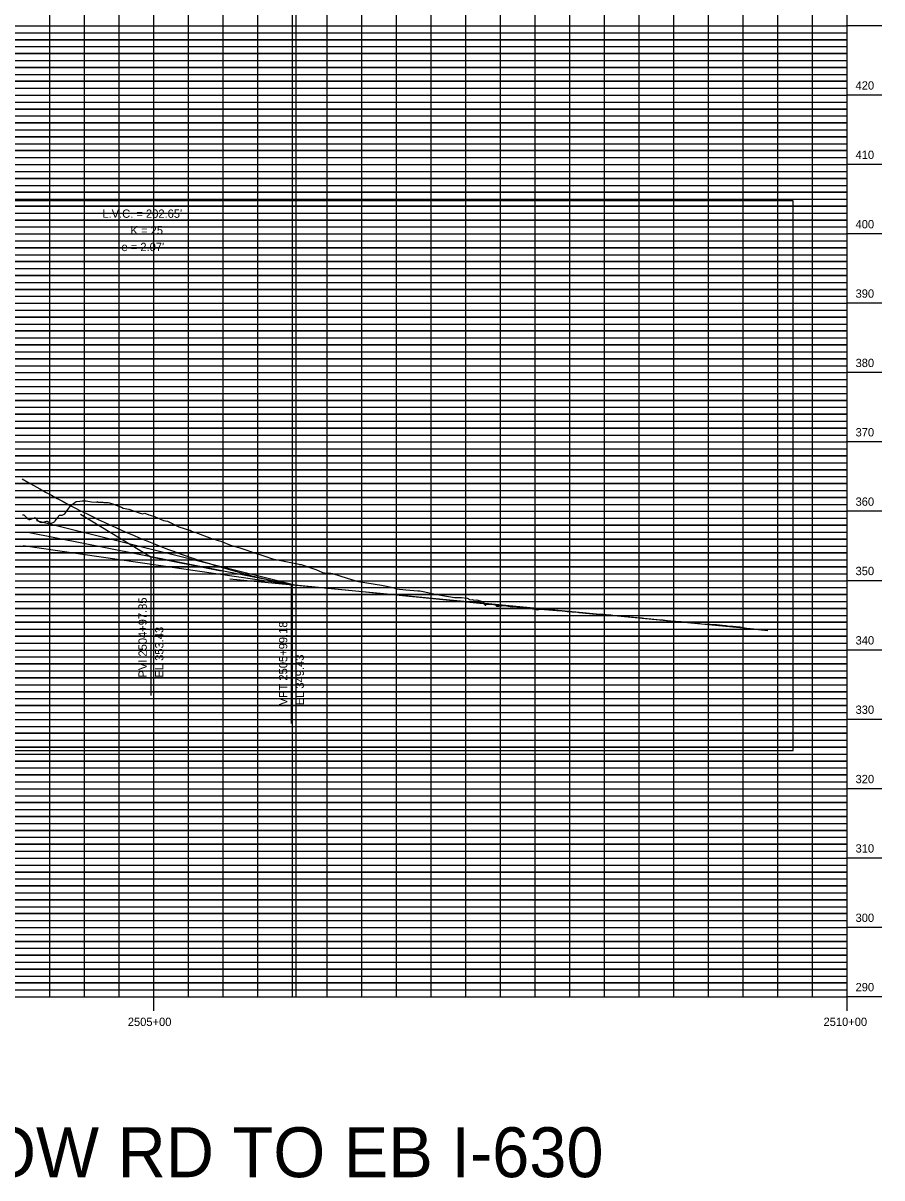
# Model space of a CAD drawing. Extents: x 1195880 to 1289360, y 2059330 to 2086925.
# Drawn here: x 1203520 to 1204139, y 2064734 to 2065566 of the extents above; entities that cross this region are included whole.
import ezdxf

# ---------------------------------------------------------------- set-up
doc = ezdxf.new("R2010")
doc.units = 0
for name, color, linetype in [('Clip', 7, 'Continuous'), ('Default', 7, 'Continuous'), ('Existing Ground PGL', 7, 'Continuous'), ('Grid', 7, 'Continuous'), ('Grid Lables', 7, 'Continuous'), ('Profile', 7, 'Continuous'), ('Profile Annotation', 7, 'Continuous')]:
    doc.layers.add(name, color=color, linetype=linetype)

msp = doc.modelspace()

# ---------------------------------------------------------------- linework, layer by layer
at = {"layer": 'Clip'}
msp.add_lwpolyline([(1203093.54, 2065041.86), (1204075.43, 2065041.86), (1204075.43, 2065438.05), (1203093.54, 2065438.05)], close=True, dxfattribs=at)
at = {"layer": 'Default'}
for p, q in [((1203716.87, 2064864.18), (1203716.87, 2065703.18)), ((1203716.87, 2065160.67), (1203529.66, 2065207.28)), ((1203716.87, 2065160.67), (1203524.56, 2065198.61)), ((1203716.87, 2065160.67), (1203520.08, 2065189.42)), ((1204057.18, 2065128.21), (1203669.12, 2065165.23)), ((1203614.36, 2064864.18), (1203716.87, 2064864.18))]:
    msp.add_line(p, q, dxfattribs=at)
at = {"layer": 'Existing Ground PGL'}
msp.add_lwpolyline([(1203519.52, 2065211.66), (1203520.46, 2065211.74), (1203520.61, 2065211.62), (1203522.65, 2065209.38), (1203523.15, 2065208.83), (1203523.62, 2065208.87), (1203523.67, 2065208.78), (1203524.39, 2065208.35), (1203524.91, 2065208.24), (1203526.32, 2065208.83), (1203527.53, 2065209.22), (1203528.75, 2065209.63), (1203530.61, 2065207.25), (1203532.4, 2065206.34), (1203532.97, 2065206.05), (1203534.42, 2065206.28), (1203537.21, 2065207.04), (1203537.28, 2065207), (1203539.88, 2065205.6), (1203540.6, 2065205.7), (1203542.16, 2065206.39), (1203542.42, 2065206.51), (1203542.84, 2065206.8), (1203543.12, 2065207.26), (1203545.24, 2065210.03), (1203545.66, 2065210.55), (1203546.12, 2065211.4), (1203547.03, 2065211.41), (1203547.66, 2065211.43), (1203548.21, 2065211.33), (1203550.13, 2065212.47), (1203551.91, 2065214.87), (1203553.04, 2065216.38), (1203554.43, 2065218.3), (1203558.21, 2065221.18), (1203560.91, 2065221.52), (1203562.58, 2065221.65), (1203565.58, 2065221.81), (1203569.27, 2065221.13), (1203573.14, 2065220.86), (1203573.47, 2065221.15), (1203574.04, 2065220.87), (1203576.15, 2065220.79), (1203577.58, 2065220.69), (1203578.35, 2065220.48), (1203581.5, 2065220.47), (1203582.25, 2065220.22), (1203583.68, 2065219.71), (1203584.02, 2065219.91), (1203584.29, 2065219.55), (1203585.33, 2065219.36), (1203591.05, 2065217.07), (1203592.16, 2065216.45), (1203596.37, 2065215.83), (1203604.47, 2065212.74), (1203606.26, 2065212.26), (1203607.82, 2065212.74), (1203610.63, 2065211.65), (1203611.59, 2065211.48), (1203614.74, 2065210.47), (1203621.27, 2065207.68), (1203624.05, 2065206.99), (1203632.39, 2065202.99), (1203640.01, 2065200.58), (1203640.41, 2065200.58), (1203641.41, 2065199.79), (1203643, 2065199.39), (1203644.6, 2065199.02), (1203655.78, 2065194.59), (1203657.17, 2065194.44), (1203660.71, 2065193.16), (1203660.8, 2065193.12), (1203662.71, 2065192.57), (1203669.55, 2065189.85), (1203676.24, 2065187.77), (1203689.07, 2065183.62), (1203690.83, 2065183.15), (1203693.65, 2065182.2), (1203694.48, 2065181.74), (1203699.98, 2065180.01), (1203717.93, 2065176.23), (1203718.97, 2065176), (1203719.37, 2065175.87), (1203719.44, 2065175.84), (1203719.57, 2065175.82), (1203720.59, 2065175.79), (1203721.27, 2065175.6), (1203730.31, 2065172.4), (1203732.26, 2065171.88), (1203736.35, 2065169.91), (1203737.47, 2065169.78), (1203742.05, 2065169.56), (1203743.13, 2065169.36), (1203753.73, 2065165.97), (1203759.15, 2065164.43), (1203760.81, 2065163.89), (1203761.98, 2065163.57), (1203778.53, 2065161.04), (1203786.72, 2065159.2), (1203789.2, 2065158.31), (1203796.16, 2065157.52), (1203804.73, 2065156.84), (1203806.18, 2065156.89), (1203808.5, 2065156.35), (1203818.45, 2065154.33), (1203825.39, 2065152.97), (1203831.2, 2065152.12), (1203831.95, 2065151.97), (1203834.22, 2065152.06), (1203836.08, 2065152.13), (1203840.31, 2065151.62), (1203841.1, 2065151.4), (1203841.54, 2065150.87), (1203842.54, 2065150.44), (1203844.09, 2065150.68), (1203844.2, 2065150.6), (1203845.08, 2065150.19), (1203847.15, 2065150.29), (1203850.98, 2065149.19), (1203852.01, 2065148), (1203853.21, 2065146.58), (1203853.78, 2065146.65), (1203853.94, 2065147.27), (1203860.24, 2065147.3), (1203861.49, 2065145.88), (1203863.16, 2065145.92), (1203867.28, 2065146.25), (1203869.83, 2065145.75), (1203872.71, 2065145.3), (1203875.64, 2065145.59), (1203879.93, 2065144.23), (1203887.3, 2065143.79), (1203889.32, 2065143.72), (1203890.72, 2065143.27), (1203893.11, 2065143.54), (1203904.97, 2065142.6), (1203905.23, 2065142.63), (1203905.56, 2065142.62), (1203905.79, 2065142.61), (1203905.98, 2065142.62), (1203906.29, 2065142.68), (1203910.93, 2065142.18), (1203912.4, 2065142.02), (1203915.85, 2065141.8), (1203917.87, 2065141.66), (1203919.8, 2065141.43), (1203920.77, 2065141.31), (1203921.22, 2065141.26), (1203922.07, 2065141.13), (1203923.37, 2065140.95), (1203925.69, 2065140.76), (1203930.6, 2065140.35), (1203933.24, 2065140.13), (1203933.75, 2065140.14), (1203934.47, 2065140.13), (1203935.5, 2065140.12), (1203935.52, 2065140.12), (1203936.37, 2065140.12), (1203938.43, 2065139.93), (1203939.51, 2065139.84), (1203940.44, 2065139.76), (1203943.8, 2065139.45), (1203945.36, 2065139.32), (1203948.21, 2065139.07), (1203950.28, 2065138.91), (1203950.82, 2065138.87), (1203951.47, 2065138.79), (1203952.7, 2065138.65), (1203954.11, 2065138.51), (1203955.14, 2065138.38), (1203955.2, 2065138.38), (1203960.12, 2065137.92), (1203965.04, 2065137.46), (1203965.54, 2065137.42), (1203966.24, 2065137.41), (1203966.53, 2065137.39), (1203967.68, 2065137.26), (1203969.95, 2065136.99), (1203970.18, 2065136.96), (1203971.75, 2065136.76), (1203972.82, 2065136.66), (1203973.58, 2065136.56), (1203974.87, 2065136.43), (1203979.79, 2065135.92), (1203979.8, 2065135.92), (1203980.08, 2065135.9), (1203980.5, 2065135.91), (1203981.18, 2065135.89), (1203981.55, 2065135.88), (1203984.71, 2065135.59), (1203984.83, 2065135.57), (1203989.63, 2065135.12), (1203990.49, 2065135.04), (1203994.55, 2065134.65), (1203994.63, 2065134.64), (1203996.56, 2065134.45), (1203999.47, 2065134.16), (1204004.39, 2065133.67), (1204006.75, 2065133.44), (1204009.31, 2065133.18), (1204013.29, 2065132.95), (1204015.54, 2065132.8), (1204017.68, 2065132.65), (1204019.04, 2065132.55), (1204019.98, 2065132.48), (1204026.49, 2065131.81), (1204026.74, 2065131.77), (1204027.11, 2065131.69), (1204027.69, 2065131.57), (1204028.28, 2065131.44), (1204030.53, 2065131.38), (1204031.97, 2065131.34), (1204034.29, 2065131.17), (1204037.22, 2065130.84), (1204038.18, 2065130.66), (1204040.22, 2065130.31), (1204043.28, 2065129.76), (1204052.47, 2065128.73), (1204057.18, 2065128.21)], dxfattribs=at)
at = {"layer": 'Grid'}
for p, q in [((1203539.36, 2064864.18), (1203539.36, 2065664.18)), ((1203564.36, 2064864.18), (1203564.36, 2065664.18)), ((1203589.36, 2064864.18), (1203589.36, 2065664.18)), ((1203614.36, 2064864.18), (1203614.36, 2065664.18)), ((1203639.36, 2064864.18), (1203639.36, 2065664.18)), ((1203664.36, 2064864.18), (1203664.36, 2065664.18)), ((1203689.36, 2064864.18), (1203689.36, 2065664.18)), ((1203714.36, 2064864.18), (1203714.36, 2065664.18)), ((1203739.36, 2064864.18), (1203739.36, 2065664.18)), ((1203764.36, 2064864.18), (1203764.36, 2065664.18)), ((1203789.36, 2064864.18), (1203789.36, 2065664.18)), ((1203814.36, 2064864.18), (1203814.36, 2065664.18)), ((1203839.36, 2064864.18), (1203839.36, 2065664.18)), ((1203864.36, 2064864.18), (1203864.36, 2065664.18)), ((1203889.36, 2064864.18), (1203889.36, 2065664.18)), ((1203914.36, 2064864.18), (1203914.36, 2065664.18)), ((1203939.36, 2064864.18), (1203939.36, 2065664.18)), ((1203964.36, 2064864.18), (1203964.36, 2065664.18)), ((1203989.36, 2064864.18), (1203989.36, 2065664.18)), ((1204014.36, 2064864.18), (1204014.36, 2065664.18)), ((1204039.36, 2064864.18), (1204039.36, 2065664.18)), ((1204064.36, 2064864.18), (1204064.36, 2065664.18)), ((1204089.36, 2064864.18), (1204089.36, 2065664.18)), ((1204114.36, 2064864.18), (1204114.36, 2065664.18)), ((1203114.36, 2065564.18), (1204114.36, 2065564.18)), ((1203114.36, 2065559.18), (1204114.36, 2065559.18)), ((1204139.36, 2065564.18), (1204114.36, 2065564.18)), ((1203114.36, 2065554.18), (1204114.36, 2065554.18)), ((1204114.36, 2065554.18), (1203114.36, 2065554.18)), ((1203114.36, 2065549.18), (1204114.36, 2065549.18)), ((1203114.36, 2065544.18), (1204114.36, 2065544.18)), ((1204114.36, 2065544.18), (1203114.36, 2065544.18)), ((1203114.36, 2065539.18), (1204114.36, 2065539.18)), ((1203114.36, 2065534.18), (1204114.36, 2065534.18)), ((1204114.36, 2065534.18), (1203114.36, 2065534.18)), ((1203114.36, 2065529.18), (1204114.36, 2065529.18)), ((1203114.36, 2065524.18), (1204114.36, 2065524.18)), ((1204114.36, 2065524.18), (1203114.36, 2065524.18)), ((1203114.36, 2065519.18), (1204114.36, 2065519.18)), ((1203114.36, 2065514.18), (1204114.36, 2065514.18)), ((1203114.36, 2065509.18), (1204114.36, 2065509.18)), ((1204139.36, 2065514.18), (1204114.36, 2065514.18)), ((1203114.36, 2065504.18), (1204114.36, 2065504.18)), ((1204114.36, 2065504.18), (1203114.36, 2065504.18)), ((1203114.36, 2065499.18), (1204114.36, 2065499.18)), ((1203114.36, 2065494.18), (1204114.36, 2065494.18)), ((1204114.36, 2065494.18), (1203114.36, 2065494.18)), ((1203114.36, 2065489.18), (1204114.36, 2065489.18)), ((1203114.36, 2065484.18), (1204114.36, 2065484.18)), ((1204114.36, 2065484.18), (1203114.36, 2065484.18)), ((1203114.36, 2065479.18), (1204114.36, 2065479.18)), ((1203114.36, 2065474.18), (1204114.36, 2065474.18)), ((1204114.36, 2065474.18), (1203114.36, 2065474.18)), ((1203114.36, 2065469.18), (1204114.36, 2065469.18)), ((1203114.36, 2065464.18), (1204114.36, 2065464.18)), ((1203114.36, 2065459.18), (1204114.36, 2065459.18)), ((1204139.36, 2065464.18), (1204114.36, 2065464.18)), ((1203114.36, 2065454.18), (1204114.36, 2065454.18)), ((1204114.36, 2065454.18), (1203114.36, 2065454.18)), ((1203114.36, 2065449.18), (1204114.36, 2065449.18)), ((1203114.36, 2065444.18), (1204114.36, 2065444.18)), ((1204114.36, 2065444.18), (1203114.36, 2065444.18)), ((1203114.36, 2065439.18), (1204114.36, 2065439.18)), ((1203114.36, 2065434.18), (1204114.36, 2065434.18)), ((1204114.36, 2065434.18), (1203114.36, 2065434.18)), ((1203114.36, 2065429.18), (1204114.36, 2065429.18)), ((1203114.36, 2065424.18), (1204114.36, 2065424.18)), ((1204114.36, 2065424.18), (1203114.36, 2065424.18)), ((1203114.36, 2065419.18), (1204114.36, 2065419.18)), ((1203114.36, 2065414.18), (1204114.36, 2065414.18)), ((1203114.36, 2065409.18), (1204114.36, 2065409.18)), ((1204139.36, 2065414.18), (1204114.36, 2065414.18)), ((1203114.36, 2065404.18), (1204114.36, 2065404.18)), ((1204114.36, 2065404.18), (1203114.36, 2065404.18)), ((1203114.36, 2065399.18), (1204114.36, 2065399.18)), ((1203114.36, 2065394.18), (1204114.36, 2065394.18)), ((1204114.36, 2065394.18), (1203114.36, 2065394.18)), ((1203114.36, 2065389.18), (1204114.36, 2065389.18)), ((1203114.36, 2065384.18), (1204114.36, 2065384.18)), ((1204114.36, 2065384.18), (1203114.36, 2065384.18)), ((1203114.36, 2065379.18), (1204114.36, 2065379.18)), ((1203114.36, 2065374.18), (1204114.36, 2065374.18)), ((1204114.36, 2065374.18), (1203114.36, 2065374.18)), ((1203114.36, 2065369.18), (1204114.36, 2065369.18)), ((1203114.36, 2065364.18), (1204114.36, 2065364.18)), ((1203114.36, 2065359.18), (1204114.36, 2065359.18)), ((1204139.36, 2065364.18), (1204114.36, 2065364.18)), ((1203114.36, 2065354.18), (1204114.36, 2065354.18)), ((1204114.36, 2065354.18), (1203114.36, 2065354.18)), ((1203114.36, 2065349.18), (1204114.36, 2065349.18)), ((1203114.36, 2065344.18), (1204114.36, 2065344.18)), ((1204114.36, 2065344.18), (1203114.36, 2065344.18)), ((1203114.36, 2065339.18), (1204114.36, 2065339.18)), ((1203114.36, 2065334.18), (1204114.36, 2065334.18)), ((1204114.36, 2065334.18), (1203114.36, 2065334.18)), ((1203114.36, 2065329.18), (1204114.36, 2065329.18)), ((1203114.36, 2065324.18), (1204114.36, 2065324.18)), ((1204114.36, 2065324.18), (1203114.36, 2065324.18)), ((1203114.36, 2065319.18), (1204114.36, 2065319.18)), ((1203114.36, 2065314.18), (1204114.36, 2065314.18)), ((1203114.36, 2065309.18), (1204114.36, 2065309.18)), ((1204139.36, 2065314.18), (1204114.36, 2065314.18)), ((1203114.36, 2065304.18), (1204114.36, 2065304.18)), ((1203114.36, 2065299.18), (1204114.36, 2065299.18)), ((1203114.36, 2065294.18), (1204114.36, 2065294.18)), ((1204114.36, 2065294.18), (1203114.36, 2065294.18)), ((1203114.36, 2065289.18), (1204114.36, 2065289.18)), ((1203114.36, 2065284.18), (1204114.36, 2065284.18)), ((1204114.36, 2065284.18), (1203114.36, 2065284.18)), ((1203114.36, 2065279.18), (1204114.36, 2065279.18)), ((1203114.36, 2065274.18), (1204114.36, 2065274.18)), ((1204114.36, 2065274.18), (1203114.36, 2065274.18)), ((1203114.36, 2065269.18), (1204114.36, 2065269.18)), ((1203114.36, 2065264.18), (1204114.36, 2065264.18)), ((1203114.36, 2065259.18), (1204114.36, 2065259.18)), ((1204139.36, 2065264.18), (1204114.36, 2065264.18)), ((1203114.36, 2065254.18), (1204114.36, 2065254.18)), ((1204114.36, 2065254.18), (1203114.36, 2065254.18)), ((1203114.36, 2065249.18), (1204114.36, 2065249.18)), ((1203114.36, 2065244.18), (1204114.36, 2065244.18)), ((1204114.36, 2065244.18), (1203114.36, 2065244.18)), ((1203114.36, 2065239.18), (1204114.36, 2065239.18)), ((1203114.36, 2065234.18), (1204114.36, 2065234.18)), ((1204114.36, 2065234.18), (1203114.36, 2065234.18)), ((1203114.36, 2065229.18), (1204114.36, 2065229.18)), ((1203114.36, 2065224.18), (1204114.36, 2065224.18)), ((1204114.36, 2065224.18), (1203114.36, 2065224.18)), ((1203114.36, 2065219.18), (1204114.36, 2065219.18)), ((1203114.36, 2065214.18), (1204114.36, 2065214.18)), ((1203114.36, 2065209.18), (1204114.36, 2065209.18)), ((1204139.36, 2065214.18), (1204114.36, 2065214.18)), ((1203114.36, 2065204.18), (1204114.36, 2065204.18)), ((1204114.36, 2065204.18), (1203114.36, 2065204.18)), ((1203114.36, 2065199.18), (1204114.36, 2065199.18)), ((1203114.36, 2065194.18), (1204114.36, 2065194.18)), ((1204114.36, 2065194.18), (1203114.36, 2065194.18)), ((1203114.36, 2065189.18), (1204114.36, 2065189.18)), ((1203114.36, 2065184.18), (1204114.36, 2065184.18)), ((1204114.36, 2065184.18), (1203114.36, 2065184.18)), ((1203114.36, 2065179.18), (1204114.36, 2065179.18)), ((1203114.36, 2065174.18), (1204114.36, 2065174.18)), ((1204114.36, 2065174.18), (1203114.36, 2065174.18)), ((1203114.36, 2065169.18), (1204114.36, 2065169.18)), ((1203114.36, 2065164.18), (1204114.36, 2065164.18)), ((1203114.36, 2065159.18), (1204114.36, 2065159.18)), ((1204139.36, 2065164.18), (1204114.36, 2065164.18)), ((1203114.36, 2065154.18), (1204114.36, 2065154.18)), ((1204114.36, 2065154.18), (1203114.36, 2065154.18)), ((1203114.36, 2065149.18), (1204114.36, 2065149.18)), ((1203114.36, 2065144.18), (1204114.36, 2065144.18)), ((1204114.36, 2065144.18), (1203114.36, 2065144.18)), ((1203114.36, 2065139.18), (1204114.36, 2065139.18)), ((1203114.36, 2065134.18), (1204114.36, 2065134.18)), ((1204114.36, 2065134.18), (1203114.36, 2065134.18)), ((1203114.36, 2065129.18), (1204114.36, 2065129.18)), ((1203114.36, 2065124.18), (1204114.36, 2065124.18)), ((1204114.36, 2065124.18), (1203114.36, 2065124.18)), ((1203114.36, 2065119.18), (1204114.36, 2065119.18)), ((1203114.36, 2065114.18), (1204114.36, 2065114.18)), ((1203114.36, 2065109.18), (1204114.36, 2065109.18)), ((1204139.36, 2065114.18), (1204114.36, 2065114.18)), ((1203114.36, 2065104.18), (1204114.36, 2065104.18)), ((1204114.36, 2065104.18), (1203114.36, 2065104.18)), ((1203114.36, 2065099.18), (1204114.36, 2065099.18)), ((1203114.36, 2065094.18), (1204114.36, 2065094.18)), ((1204114.36, 2065094.18), (1203114.36, 2065094.18)), ((1203114.36, 2065089.18), (1204114.36, 2065089.18)), ((1203114.36, 2065084.18), (1204114.36, 2065084.18)), ((1204114.36, 2065084.18), (1203114.36, 2065084.18)), ((1203114.36, 2065079.18), (1204114.36, 2065079.18)), ((1203114.36, 2065074.18), (1204114.36, 2065074.18)), ((1204114.36, 2065074.18), (1203114.36, 2065074.18)), ((1203114.36, 2065069.18), (1204114.36, 2065069.18)), ((1203114.36, 2065064.18), (1204114.36, 2065064.18)), ((1203114.36, 2065059.18), (1204114.36, 2065059.18)), ((1204139.36, 2065064.18), (1204114.36, 2065064.18)), ((1203114.36, 2065054.18), (1204114.36, 2065054.18)), ((1204114.36, 2065054.18), (1203114.36, 2065054.18)), ((1203114.36, 2065049.18), (1204114.36, 2065049.18)), ((1203114.36, 2065044.18), (1204114.36, 2065044.18)), ((1204114.36, 2065044.18), (1203114.36, 2065044.18)), ((1203114.36, 2065039.18), (1204114.36, 2065039.18)), ((1203114.36, 2065034.18), (1204114.36, 2065034.18)), ((1204114.36, 2065034.18), (1203114.36, 2065034.18)), ((1203114.36, 2065029.18), (1204114.36, 2065029.18)), ((1203114.36, 2065024.18), (1204114.36, 2065024.18)), ((1204114.36, 2065024.18), (1203114.36, 2065024.18)), ((1203114.36, 2065019.18), (1204114.36, 2065019.18)), ((1203114.36, 2065014.18), (1204114.36, 2065014.18)), ((1203114.36, 2065009.18), (1204114.36, 2065009.18)), ((1204139.36, 2065014.18), (1204114.36, 2065014.18)), ((1203114.36, 2065004.18), (1204114.36, 2065004.18)), ((1204114.36, 2065004.18), (1203114.36, 2065004.18)), ((1203114.36, 2064999.18), (1204114.36, 2064999.18)), ((1203114.36, 2064994.18), (1204114.36, 2064994.18)), ((1204114.36, 2064994.18), (1203114.36, 2064994.18)), ((1203114.36, 2064989.18), (1204114.36, 2064989.18)), ((1203114.36, 2064984.18), (1204114.36, 2064984.18)), ((1204114.36, 2064984.18), (1203114.36, 2064984.18)), ((1203114.36, 2064979.18), (1204114.36, 2064979.18)), ((1203114.36, 2064974.18), (1204114.36, 2064974.18)), ((1204114.36, 2064974.18), (1203114.36, 2064974.18)), ((1203114.36, 2064969.18), (1204114.36, 2064969.18)), ((1203114.36, 2064964.18), (1204114.36, 2064964.18)), ((1203114.36, 2064959.18), (1204114.36, 2064959.18)), ((1204139.36, 2064964.18), (1204114.36, 2064964.18)), ((1203114.36, 2064954.18), (1204114.36, 2064954.18)), ((1204114.36, 2064954.18), (1203114.36, 2064954.18)), ((1203114.36, 2064949.18), (1204114.36, 2064949.18)), ((1203114.36, 2064944.18), (1204114.36, 2064944.18)), ((1204114.36, 2064944.18), (1203114.36, 2064944.18)), ((1203114.36, 2064939.18), (1204114.36, 2064939.18)), ((1203114.36, 2064934.18), (1204114.36, 2064934.18)), ((1204114.36, 2064934.18), (1203114.36, 2064934.18)), ((1203114.36, 2064929.18), (1204114.36, 2064929.18)), ((1203114.36, 2064924.18), (1204114.36, 2064924.18)), ((1204114.36, 2064924.18), (1203114.36, 2064924.18)), ((1203114.36, 2064919.18), (1204114.36, 2064919.18)), ((1203114.36, 2064914.18), (1204114.36, 2064914.18)), ((1203114.36, 2064909.18), (1204114.36, 2064909.18)), ((1204139.36, 2064914.18), (1204114.36, 2064914.18)), ((1203114.36, 2064904.18), (1204114.36, 2064904.18)), ((1204114.36, 2064904.18), (1203114.36, 2064904.18)), ((1203114.36, 2064899.18), (1204114.36, 2064899.18)), ((1203114.36, 2064894.18), (1204114.36, 2064894.18)), ((1204114.36, 2064894.18), (1203114.36, 2064894.18)), ((1203114.36, 2064889.18), (1204114.36, 2064889.18)), ((1203114.36, 2064884.18), (1204114.36, 2064884.18)), ((1204114.36, 2064884.18), (1203114.36, 2064884.18)), ((1203114.36, 2064879.18), (1204114.36, 2064879.18)), ((1203114.36, 2064874.18), (1204114.36, 2064874.18)), ((1204114.36, 2064874.18), (1203114.36, 2064874.18)), ((1203114.36, 2064869.18), (1204114.36, 2064869.18)), ((1203539.36, 2064864.18), (1203539.36, 2064867.18)), ((1203564.36, 2064864.18), (1203564.36, 2064867.18)), ((1203589.36, 2064864.18), (1203589.36, 2064867.18)), ((1203639.36, 2064864.18), (1203639.36, 2064867.18)), ((1203664.36, 2064864.18), (1203664.36, 2064867.18)), ((1203689.36, 2064864.18), (1203689.36, 2064867.18)), ((1203714.36, 2064864.18), (1203714.36, 2064867.18)), ((1203739.36, 2064864.18), (1203739.36, 2064867.18)), ((1203764.36, 2064864.18), (1203764.36, 2064867.18)), ((1203789.36, 2064864.18), (1203789.36, 2064867.18)), ((1203814.36, 2064864.18), (1203814.36, 2064867.18)), ((1203839.36, 2064864.18), (1203839.36, 2064867.18)), ((1203864.36, 2064864.18), (1203864.36, 2064867.18)), ((1203889.36, 2064864.18), (1203889.36, 2064867.18)), ((1203914.36, 2064864.18), (1203914.36, 2064867.18)), ((1203939.36, 2064864.18), (1203939.36, 2064867.18)), ((1203964.36, 2064864.18), (1203964.36, 2064867.18)), ((1203989.36, 2064864.18), (1203989.36, 2064867.18)), ((1204014.36, 2064864.18), (1204014.36, 2064867.18)), ((1204039.36, 2064864.18), (1204039.36, 2064867.18)), ((1204064.36, 2064864.18), (1204064.36, 2064867.18)), ((1204089.36, 2064864.18), (1204089.36, 2064867.18)), ((1203114.36, 2064864.18), (1204114.36, 2064864.18)), ((1203614.36, 2064854.18), (1203614.36, 2064864.18)), ((1204139.36, 2064864.18), (1204114.36, 2064864.18)), ((1204114.36, 2064854.18), (1204114.36, 2064864.18))]:
    msp.add_line(p, q, dxfattribs=at)
at = {"layer": 'Profile'}
msp.add_line((1203713.54, 2065161.33), (1203893.11, 2065143.54), dxfattribs=at)
msp.add_lwpolyline([(1203519.34, 2065237.72), (1203523.56, 2065235.25), (1203527.78, 2065232.82), (1203532, 2065230.42), (1203536.22, 2065228.06), (1203540.45, 2065225.73), (1203544.67, 2065223.44), (1203548.89, 2065221.18), (1203553.11, 2065218.97), (1203557.33, 2065216.78), (1203561.55, 2065214.64), (1203565.78, 2065212.52), (1203570, 2065210.45), (1203574.22, 2065208.41), (1203578.44, 2065206.41), (1203582.66, 2065204.44), (1203586.89, 2065202.51), (1203591.11, 2065200.62), (1203595.33, 2065198.76), (1203599.55, 2065196.93), (1203603.77, 2065195.15), (1203607.99, 2065193.4), (1203616.44, 2065190), (1203620.66, 2065188.36), (1203624.88, 2065186.75), (1203629.1, 2065185.18), (1203633.33, 2065183.65), (1203637.55, 2065182.15), (1203641.77, 2065180.69), (1203645.99, 2065179.26), (1203650.21, 2065177.87), (1203654.44, 2065176.51), (1203658.66, 2065175.2), (1203662.88, 2065173.91), (1203667.1, 2065172.67), (1203671.32, 2065171.46), (1203675.54, 2065170.28), (1203679.77, 2065169.14), (1203683.99, 2065168.04), (1203688.21, 2065166.97), (1203692.43, 2065165.94), (1203696.65, 2065164.95), (1203700.88, 2065163.99), (1203705.1, 2065163.06), (1203709.32, 2065162.18), (1203713.54, 2065161.33)], dxfattribs=at)
at = {"layer": 'Profile Annotation'}
for p, q in [((1203561.55, 2065212.04), (1203612.22, 2065181.32)), ((1203612.22, 2065181.32), (1203662.88, 2065171.32)), ((1203612.22, 2065181.32), (1203612.22, 2065081.32)), ((1203713.54, 2065061.33), (1203713.54, 2065161.33))]:
    msp.add_line(p, q, dxfattribs=at)

# ---------------------------------------------------------------- texts
at = {"layer": 'Default'}
msp.add_text('RAMP JOHN BARROW RD TO EB I-630', height=36, rotation=360, dxfattribs=at).set_placement((1203061.28, 2064734.18))
at = {"layer": 'Grid Lables'}
for s, p in [('420', (1204120.36, 2065518.18)), ('410', (1204120.36, 2065468.18)), ('400', (1204120.36, 2065418.18)), ('390', (1204120.36, 2065368.18)), ('380', (1204120.36, 2065318.18)), ('370', (1204120.36, 2065268.18)), ('360', (1204120.36, 2065218.18)), ('350', (1204120.36, 2065168.18)), ('340', (1204120.36, 2065118.18)), ('330', (1204120.36, 2065068.18)), ('320', (1204120.36, 2065018.18)), ('310', (1204120.36, 2064968.18)), ('300', (1204120.36, 2064918.18)), ('290', (1204120.36, 2064868.18)), ('2505+00', (1203595.54, 2064843.18)), ('2510+00', (1204097.24, 2064843.18))]:
    msp.add_text(s, height=6, dxfattribs=at).set_placement(p)
at = {"layer": 'Profile Annotation'}
for s, p in [("L.V.C. = 202.65'", (1203577.21, 2065425.77)), ('K = 25', (1203597.52, 2065413.77)), ("e = 2.07'", (1203591, 2065401.77))]:
    msp.add_text(s, height=6, dxfattribs=at).set_placement(p)
for s, p in [('PVI 2504+97.85', (1203609.22, 2065094.32)), ('VPT 2505+99.18', (1203710.54, 2065074.33)), ('EL 353.43', (1203621.22, 2065094.32)), ('EL 349.43', (1203722.54, 2065074.33))]:
    msp.add_text(s, height=6, rotation=90, dxfattribs=at).set_placement(p)

doc.saveas('drawing.dxf')
